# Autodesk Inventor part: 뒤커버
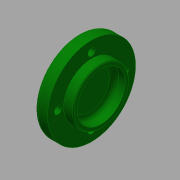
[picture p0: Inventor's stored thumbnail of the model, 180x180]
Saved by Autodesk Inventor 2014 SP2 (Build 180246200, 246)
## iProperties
Created: 2015-12
Part Number: 뒤커버
Material: 알루미늄 6061
Document SubType Name: Modeling
Designer: mduedu
Density: 2.71 g/cm^3
Appearance: 진녹색
Author: mduedu
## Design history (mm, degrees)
sketch "스케치1"
  geometry: L1 (0, 0)-(14, 0); L2 (14, 0)-(14, 17.5); L3 (14, 17.5)-(8, 17.5); L4 (8, 17.5)-(8, 27.5); L5 (8, 27.5)-(0, 27.5); L6 (0, 27.5)-(0, 0)
  constraints: 12 end point, 4 parallel, 1 horizontal, 1 perpendicular
  dimensions: "d0" = 14 distance between parallel lines of L2 L6; "d2" = 8 distance of L4.end L5.end; "d3" = 55 diameter of L5 L1; "d4" = 35 diameter of L3 L1
revolve "회전1" sketch "스케치1" stored, may be unused: angle "d5" = 90 deg
hole "구멍1" diameter "d8" = 30; stored, may be unused: countersink angle "d12" = 90 deg, drill point angle "d14" = 0 deg; dims "d9" = 6, "d10" = 4, "d11" = 2, "d13" = 7, "d39" = 10, "d40" = 10
fillet "모깎기3" dims "d38" = 2
fillet "모깎기4" dims "d41" = 3
chamfer "모따기2" distance "d42" = 0.5; stored, may be unused: second distance "d43" = 2, angle "d44" = 45 deg
sketch "스케치2" dims "d45" = 42
  geometry: 6 further points
  constraints: 2 vertical alignment, 1 coincident, 7 other
  dimensions: "d48" = 360 deg dimension on point (0, 0) point (0, 21) (derived)
sketch "스케치3"
  geometry: 4 further points
hole "구멍4" sketch "스케치3" at (-21, 0), (0, -21), (21, 0), (0, 21) diameter "d50" = 4.5; stored, may be unused: countersink angle "d54" = 90 deg, drill point angle "d56" = 0 deg; dims "d51" = 6, "d52" = 8, "d53" = 4.6, "d55" = 8
node "솔리드1"
